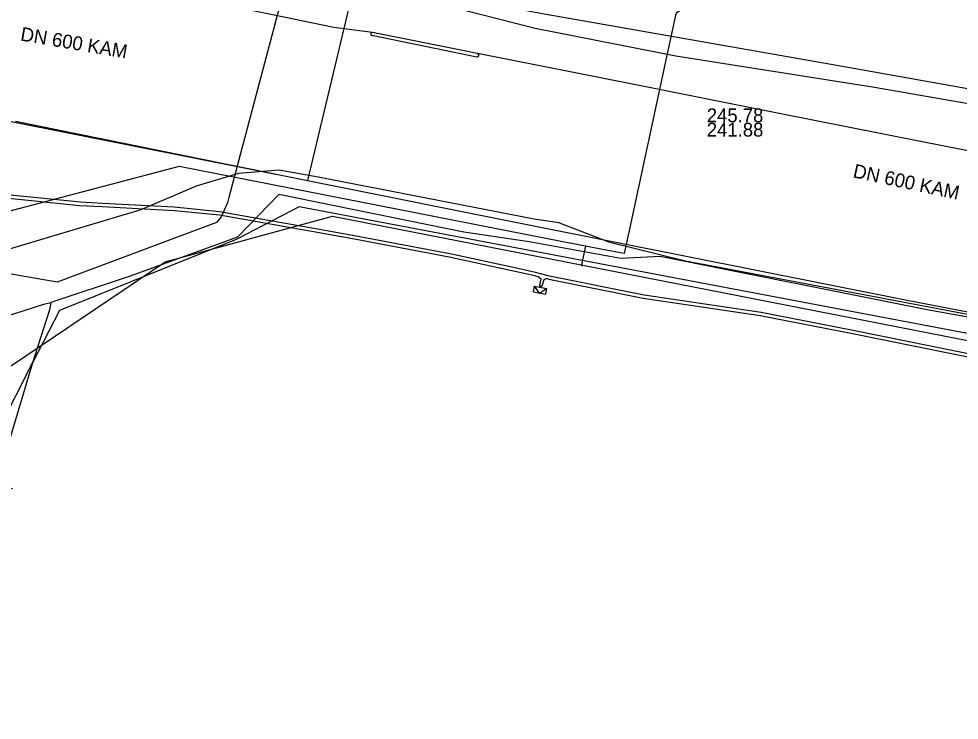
# Model space of a CAD drawing. Extents: x -599951 to -598963, y -1164095 to -1162939.
# Drawn here: x -599648.8 to -599594.4, y -1163126.2 to -1163085.6 of the extents above; entities that cross this region are included whole.
import ezdxf

# ---------------------------------------------------------------- set-up
doc = ezdxf.new("R2010")
doc.units = 0
for name, color, linetype in [('31', 7, 'Continuous'), ('Vrstva 12', 7, 'Continuous'), ('Vrstva 13', 7, 'Continuous'), ('Vrstva 19', 7, 'Continuous'), ('Vrstva 25', 7, 'Continuous'), ('Vrstva 42', 7, 'Continuous'), ('Vrstva 43', 7, 'Continuous'), ('Vrstva 44', 7, 'Continuous'), ('Vrstva 55', 7, 'Continuous'), ('Vrstva 58', 7, 'Continuous')]:
    doc.layers.add(name, color=color, linetype=linetype)

# ---------------------------------------------------------------- blocks, each defined once
blk = doc.blocks.new('NN630')
at = {"layer": '31'}
for points in [[(-0.003, -0.7), (-0.703, 0)], [(-0.703, -0.7), (-0.703, 0), (0.697, 0), (0.697, -0.7)], [(-0.003, -0.7), (0.697, 0)], [(-0.703, -0.7), (0.697, -0.7)]]:
    blk.add_lwpolyline(points, dxfattribs=at)

msp = doc.modelspace()

# ---------------------------------------------------------------- linework, layer by layer
at = {"layer": 'Vrstva 12'}
for points in [[(-599664.63, -1163105.36), (-599654.17, -1163106.92), (-599649.28, -1163105.66), (-599640.38, -1163099.65), (-599630.69, -1163097), (-599583.49, -1163106.26), (-599580.39, -1163090.87)], [(-599581.77, -1163105.29), (-599584.59, -1163104.75), (-599585.75, -1163104.32), (-599596.28, -1163102.44), (-599611.72, -1163099.35), (-599614, -1163099.46), (-599619.31, -1163098.5), (-599623.09, -1163097.93), (-599633.8, -1163095.75), (-599636.2, -1163098.22), (-599642.46, -1163100.51), (-599647, -1163102)], [(-599607.48, -1163101.23), (-599632.63, -1163096.47), (-599636.27, -1163098.36), (-599646.49, -1163102.47), (-599648.05, -1163105.5)], [(-599581.77, -1163105.29), (-599581.92, -1163106.07), (-599607.48, -1163101.23)], [(-599653.27, -1163103.99), (-599652.39, -1163103.7), (-599647.4, -1163102.1)], [(-599647.4, -1163102.1), (-599647, -1163102)], [(-599647, -1163102), (-599647.08, -1163102.43)], [(-599647.08, -1163102.43), (-599648.05, -1163105.5)], [(-599660.09, -1163106.56), (-599649.99, -1163109.28), (-599648.05, -1163105.5)], [(-599648.05, -1163105.5), (-599649.32, -1163109.76), (-599649.99, -1163111.85), (-599650.15, -1163112.48), (-599649.67, -1163112.79), (-599649.22, -1163112.75)]]:
    msp.add_lwpolyline(points, dxfattribs=at)
at = {"layer": 'Vrstva 13'}
for p, q in [((-599616.056, -1163098.75), (-599617.355, -1163098.489)), ((-599616.056, -1163098.75), (-599616.22, -1163099.54)), ((-599615.07, -1163098.93), (-599616.056, -1163098.75))]:
    msp.add_line(p, q, dxfattribs=at)
for points in [[(-599459.073, -1162939.4), (-599465.76, -1162949.91), (-599471.32, -1162957.71), (-599475.35, -1162963.72), (-599519.14, -1163015.26), (-599531.15, -1163028.03), (-599549.5, -1163049.13), (-599563.156, -1163063.255), (-599573.78, -1163069.24), (-599580.56, -1163072.79), (-599592.642, -1163078.384), (-599610.28, -1163084.85), (-599610.821, -1163085.298), (-599611.357, -1163087.777), (-599613.546, -1163097.928), (-599613.81, -1163099.161), (-599615.07, -1163098.93)], [(-599617.355, -1163098.489), (-599639.566, -1163094.136), (-599650.192, -1163096.923), (-599678.181, -1163091.895), (-599723.934, -1163082.934)], [(-599616.22, -1163099.54), (-599616.282, -1163099.862), (-599616.29, -1163099.909)]]:
    msp.add_lwpolyline(points, dxfattribs=at)
at = {"layer": 'Vrstva 19'}
msp.add_lwpolyline([(-599616.59, -1163080.56), (-599617.17, -1163080.84), (-599617.665, -1163080.979), (-599617.92, -1163081.05), (-599626.46, -1163080.11), (-599632.18, -1163079.15), (-599632.71, -1163080.94), (-599636.689, -1163095.936), (-599636.767, -1163096.229), (-599637.141, -1163097.046), (-599637.398, -1163097.371), (-599646.619, -1163100.828), (-599651.745, -1163099.938), (-599653.913, -1163099.562), (-599659.58, -1163098.691), (-599677.173, -1163096.012), (-599677.385, -1163095.98), (-599688.754, -1163093.782), (-599709.701, -1163088.962), (-599717.665, -1163087.571), (-599719.652, -1163087.233), (-599734.599, -1163084.885), (-599741.561, -1163083.741), (-599749.337, -1163082.368)], dxfattribs=at)
at = {"layer": 'Vrstva 25'}
msp.add_lwpolyline([(-599586.873, -1163104.025), (-599610.256, -1163099.613), (-599614.644, -1163098.537), (-599617.595, -1163097.394), (-599619.024, -1163097.18), (-599631.522, -1163094.749), (-599633.787, -1163094.354), (-599636.128, -1163094.539), (-599638.584, -1163095.271), (-599641.788, -1163096.644), (-599652.063, -1163099.704)], dxfattribs=at)
at = {"layer": 'Vrstva 42'}
for p, q in [((-599628.42, -1163086.54), (-599622.34, -1163087.78)), ((-599622.3, -1163087.6), (-599628.37, -1163086.37))]:
    msp.add_line(p, q, dxfattribs=at)
for points in [[(-599628.37, -1163086.37), (-599630.61, -1163086.08), (-599634.63, -1163085.25), (-599636.56, -1163084.87), (-599640.58, -1163084.16), (-599643.84, -1163083.58), (-599649.85, -1163082.43), (-599651.16, -1163082.29), (-599653.26, -1163082.4), (-599655.29, -1163082.76), (-599656.81, -1163083.2), (-599658.59, -1163083.79), (-599659.9, -1163084.03), (-599660.91, -1163084.02), (-599664.47, -1163083.38), (-599665.15, -1163083.2), (-599673.67, -1163081.73), (-599681.77, -1163080.21), (-599692, -1163078.2), (-599702.95, -1163076.09), (-599714.36, -1163073.83), (-599725, -1163071.8), (-599736.94, -1163069.5), (-599747.67, -1163067.47)], [(-599588.13, -1163094.37), (-599596.76, -1163092.67), (-599604.85, -1163091.07), (-599613.13, -1163089.41), (-599622.3, -1163087.6)], [(-599605.893, -1163102.581), (-599612.653, -1163101.576), (-599618.13, -1163100.472), (-599618.939, -1163100.262), (-599620.145, -1163099.998), (-599623.805, -1163099.201), (-599629.424, -1163098.144), (-599632.093, -1163097.66), (-599637.236, -1163096.751), (-599639.852, -1163096.49), (-599643.999, -1163096.273), (-599645.273, -1163096.206), (-599650.34, -1163095.698)], [(-599593.156, -1163105.321), (-599600.602, -1163103.828), (-599605.944, -1163102.776), (-599612.717, -1163101.769), (-599618.17, -1163100.668), (-599618.299, -1163100.626), (-599618.469, -1163100.69), (-599618.554, -1163101.004), (-599618.65, -1163101.12), (-599618.687, -1163101.002), (-599618.619, -1163100.66), (-599618.786, -1163100.513), (-599618.981, -1163100.458), (-599623.947, -1163099.378), (-599629.318, -1163098.368), (-599632.008, -1163097.878), (-599637.239, -1163096.954), (-599639.842, -1163096.692), (-599644.028, -1163096.472), (-599645.327, -1163096.403), (-599650.377, -1163095.895)], [(-599593.127, -1163105.123), (-599600.556, -1163103.633), (-599605.893, -1163102.581)]]:
    msp.add_lwpolyline(points, dxfattribs=at)
for centre, radius, start, end in [((-599628.395, -1163086.455), 0.0886, 73.6101, 263.338), ((-599622.32, -1163087.69), 0.0922, 257.4409, 79.6022)]:
    msp.add_arc(centre, radius, start, end, dxfattribs=at)
at = {"layer": 'Vrstva 44'}
msp.add_lwpolyline([(-599748.035, -1163058.372), (-599724.432, -1163062.801), (-599713.25, -1163065.019), (-599697.914, -1163067.775), (-599682.25, -1163070.502), (-599666.755, -1163073.705), (-599660.586, -1163074.868), (-599629.566, -1163083.973), (-599624.124, -1163084.818), (-599618.967, -1163086.117), (-599610.817, -1163087.733), (-599599.443, -1163089.526), (-599589.445, -1163091.26)], dxfattribs=at)
at = {"layer": 'Vrstva 55'}
for points in [[(-599664.02, -1163109.18), (-599663.64, -1163108.8), (-599661.8, -1163109.07), (-599659.02, -1163095.62), (-599655.62, -1163093.59), (-599653.59, -1163093.99), (-599652.81, -1163090.829), (-599632.13, -1163094.94), (-599629.28, -1163083.06), (-599623.65, -1163081.39), (-599622.96, -1163083.4)], [(-599649.04, -1163091.51), (-599632.14, -1163094.95), (-599618.855, -1163097.599)], [(-599618.855, -1163097.599), (-599597.44, -1163101.87), (-599562.87, -1163108.53), (-599528.51, -1163115.32), (-599493.94, -1163122.04), (-599459.65, -1163128.7), (-599425.29, -1163135.35), (-599390.79, -1163142.01), (-599379.04, -1163144.18), (-599370.08, -1163145.68), (-599333.88, -1163152.87), (-599287.5, -1163161.7), (-599253.07, -1163168.09), (-599247.97, -1163169.04), (-599246.945, -1163169.092), (-599247.03, -1163167.178), (-599245.243, -1163166.795)]]:
    msp.add_lwpolyline(points, dxfattribs=at)
at = {"layer": 'Vrstva 58'}
msp.add_lwpolyline([(-599752.946, -1163056.655), (-599739.506, -1163059.075), (-599723.286, -1163062.295), (-599708.496, -1163065.135), (-599689.456, -1163068.595), (-599664.066, -1163073.415), (-599653.826, -1163076.325), (-599629.566, -1163083.125), (-599618.646, -1163085.265), (-599601.496, -1163088.275), (-599589.936, -1163090.325), (-599585.106, -1163090.775), (-599584.226, -1163091.175), (-599583.576, -1163092.035), (-599585.966, -1163102.435), (-599586.306, -1163105.375), (-599586.196, -1163105.675), (-599585.406, -1163105.925), (-599563.046, -1163110.065), (-599544.516, -1163113.655), (-599517.146, -1163118.855), (-599483.776, -1163125.315), (-599467.296, -1163128.595), (-599449.626, -1163131.895)], dxfattribs=at)
msp.add_lwpolyline([(-599752.946, -1163056.655), (-599739.506, -1163059.075), (-599723.286, -1163062.295), (-599708.496, -1163065.135), (-599689.456, -1163068.595), (-599664.066, -1163073.415), (-599653.826, -1163076.325), (-599629.566, -1163083.125), (-599618.646, -1163085.265), (-599601.496, -1163088.275), (-599589.936, -1163090.325), (-599585.106, -1163090.775), (-599584.226, -1163091.175), (-599583.576, -1163092.035), (-599585.966, -1163102.435), (-599586.306, -1163105.375), (-599586.196, -1163105.675), (-599585.406, -1163105.925), (-599563.046, -1163110.065), (-599544.516, -1163113.655), (-599517.146, -1163118.855), (-599483.776, -1163125.315), (-599467.296, -1163128.595), (-599449.626, -1163131.895)], dxfattribs=at)

# ---------------------------------------------------------------- block references
at = {"layer": 'Vrstva 43', "xscale": 0.5000000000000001, "yscale": 0.5, "rotation": -10.999999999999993}
msp.add_blockref('NN630', (-599618.65, -1163101.12), dxfattribs=at)

# ---------------------------------------------------------------- texts
at = {"layer": 'Vrstva 12'}
for rotation, p in [(350.3064, (-599648.792, -1163086.836)), (347.9108, (-599600.613, -1163094.753))]:
    msp.add_text('DN 600 KAM', height=0.8, rotation=rotation, dxfattribs=at).set_placement(p)
for s, p in [('245.78', (-599609.031, -1163091.57)), ('241.88', (-599609.031, -1163092.402))]:
    msp.add_text(s, height=0.8, dxfattribs=at).set_placement(p)

doc.saveas('drawing.dxf')
